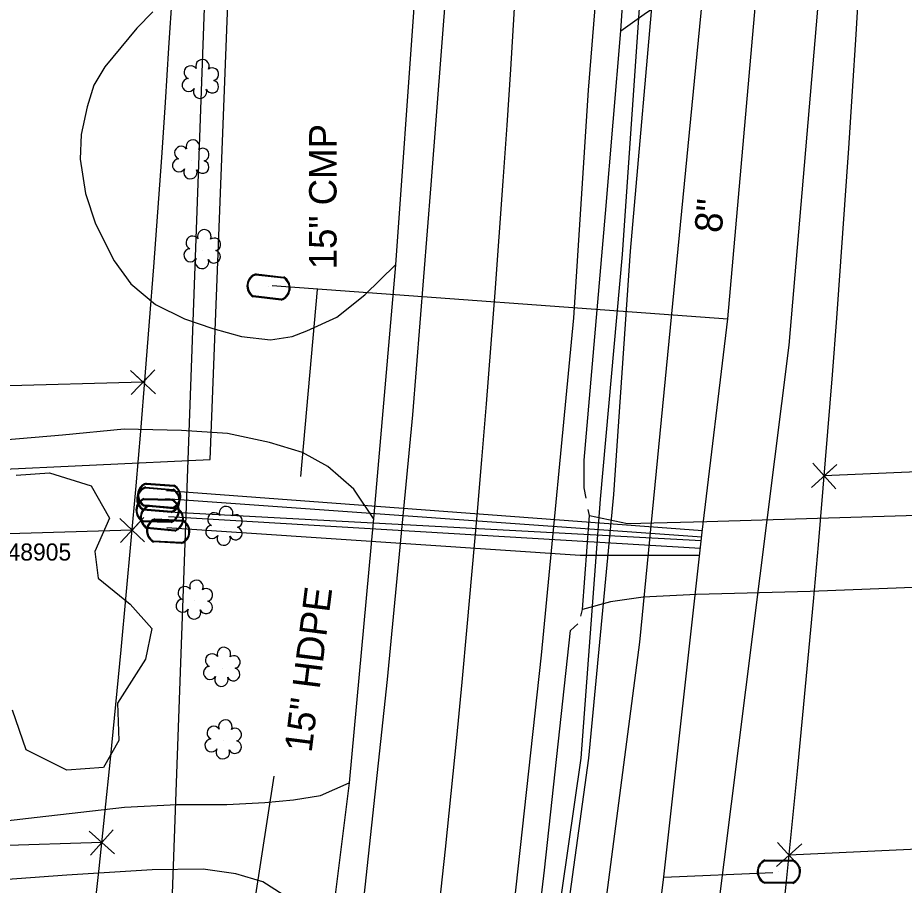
# Model space of a CAD drawing. Extents: x 3040896 to 3051146, y 687568 to 732976.
# Drawn here: x 3050359.9 to 3050489.4, y 692126.7 to 692253.4 of the extents above; entities that cross this region are included whole.
import ezdxf

# ---------------------------------------------------------------- set-up
doc = ezdxf.new("R2010")
doc.units = 0
for name, color, linetype in [('Exist Horizontal Alignment', 7, 'Continuous'), ('Exist Property Corner CELL', 7, 'Continuous'), ('Exist Property Line', 7, 'Continuous'), ('Exist Right of Way Easement Line', 7, 'Continuous'), ('Exist Right of Way Line', 7, 'Continuous'), ('Exist Roads Change in Surface', 7, 'Continuous'), ('Exist Roads EOP', 7, 'Continuous'), ('Exist Roads EOP Other', 7, 'Continuous'), ('Exist Roads EOT', 7, 'Continuous'), ('Exist Roads Soil', 7, 'Continuous'), ('Exist Structure Minor Pipes CMP 15 Inch', 7, 'Continuous'), ('Exist Structure Minor Pipes CMP 15 Inch Text', 7, 'Continuous'), ('Exist Structure Minor Pipes HDPE 15 Inch', 7, 'Continuous'), ('Exist Structure Minor Pipes HDPE 15 Inch Text', 7, 'Continuous'), ('Exist Utilities Power Joint Use Telephone Cogo Comment', 7, 'Continuous'), ('Exist Utilities Telephone UG Cable', 7, 'Continuous'), ('Exist Utilities Telephone UG Conduit SUE', 7, 'Continuous'), ('Exist Utilities Water Meter CELL', 7, 'Continuous'), ('Exist Utilities Water UG Line SUE', 7, 'Continuous'), ('Exist Utilities Water UG Line SUE Text', 7, 'Continuous'), ('Exist Vegetation Hedge Row', 7, 'Continuous'), ('Exist Vegetation Shrub CELL', 7, 'Continuous')]:
    doc.layers.add(name, color=color, linetype=linetype)

msp = doc.modelspace()

# ---------------------------------------------------------------- linework, layer by layer
at = {"layer": 'Exist Horizontal Alignment'}
msp.add_arc((3047548.29, 692429.83), 2889.5, 341.451, 2.18494, dxfattribs=at)
at = {"layer": 'Exist Property Corner CELL'}
for p, q in [((3050378.24, 692200.16), (3050378.24, 692200.16)), ((3050477.7, 692186.44), (3050477.7, 692186.44)), ((3050376.65, 692178.54), (3050376.65, 692178.54)), ((3050372.22, 692132.91), (3050372.22, 692132.91)), ((3050472.57, 692131.06), (3050472.57, 692131.06))]:
    msp.add_line(p, q, dxfattribs=at)
for points in [[(3050376.52, 692198.34), (3050379.95, 692201.97), (3050378.24, 692200.16), (3050376.42, 692201.87), (3050380.05, 692198.44)], [(3050476.03, 692188.3), (3050479.37, 692184.58), (3050477.7, 692186.44), (3050479.56, 692188.11), (3050475.84, 692184.77)], [(3050374.94, 692176.72), (3050378.36, 692180.36), (3050376.65, 692178.54), (3050374.83, 692180.25), (3050378.47, 692176.83)], [(3050374.08, 692131.24), (3050370.37, 692134.59), (3050372.22, 692132.91), (3050370.55, 692131.06), (3050373.9, 692134.77)], [(3050470.9, 692132.92), (3050474.24, 692129.2), (3050472.57, 692131.06), (3050474.43, 692132.73), (3050470.71, 692129.39)]]:
    msp.add_lwpolyline(points, dxfattribs=at)
at = {"layer": 'Exist Property Line'}
for p, q in [((3050378.24, 692200.16), (3050092.29, 692192.16)), ((3050586.46, 692191.46), (3050477.7, 692186.44)), ((3050376.65, 692178.54), (3050103.02, 692170.18)), ((3050609.02, 692137.42), (3050472.57, 692131.06))]:
    msp.add_line(p, q, dxfattribs=at)
at = {"layer": 'Exist Right of Way Easement Line'}
msp.add_line((3050372.22, 692132.91), (3049833.74, 692116.46), dxfattribs=at)
at = {"layer": 'Exist Right of Way Line'}
for radius in [2939.5, 2839.5]:
    msp.add_arc((3047548.29, 692429.83), radius, 341.451, 2.18494, dxfattribs=at)
at = {"layer": 'Exist Roads Change in Surface'}
msp.add_lwpolyline([(3050442.16, 692165.96), (3050442.41, 692166.93), (3050443.42, 692180.65), (3050443.25, 692181.54)], dxfattribs=at)
at = {"layer": 'Exist Roads EOP'}
for points in [[(3050442.94, 692183.19), (3050442.64, 692184.72), (3050442.67, 692188.75), (3050445.75, 692224.78), (3050448.02, 692251.48), (3050450.28, 692285.57), (3050451.67, 692312.92), (3050452.54, 692332.34), (3050452.6, 692339.09)], [(3050422.57, 692333.6), (3050421.5, 692308.19), (3050419.78, 692278.79), (3050417.77, 692254.87), (3050415.09, 692217.27), (3050411.91, 692180.22), (3050408.34, 692141.62), (3050405.23, 692116.7), (3050399.7, 692069.33), (3050393.06, 692018.15), (3050381.68, 691947.12), (3050378.88, 691928.21), (3050374.32, 691903.28), (3050369.25, 691876.97), (3050364.29, 691851.91)], [(3050431.59, 692084.53), (3050436.86, 692128.88), (3050440.66, 692163.88), (3050441.74, 692164.87)]]:
    msp.add_lwpolyline(points, dxfattribs=at)
at = {"layer": 'Exist Roads EOP Other'}
for points in [[(3050443.42, 692180.65), (3050448.98, 692179.5), (3050460.56, 692179.81), (3050489.68, 692180.66), (3050518.22, 692181.24), (3050547.88, 692182.08), (3050581.57, 692183.6), (3050589.57, 692183.89), (3050596.75, 692184.89), (3050606.36, 692186.1), (3050616.41, 692188.04), (3050625.67, 692188.73), (3050626.42, 692177.84)], [(3050613.16, 692158.9), (3050612.58, 692160.76), (3050612.11, 692161.63), (3050611.46, 692161.59), (3050610.6, 692161.03), (3050610.09, 692160.39), (3050609.91, 692157.91), (3050610.52, 692146.62), (3050596.9, 692147.08), (3050595.89, 692162.54), (3050595.39, 692166.27), (3050594.24, 692169.11), (3050591.91, 692171.51), (3050588.91, 692172.01), (3050579.02, 692172.64), (3050561.96, 692172.23), (3050534.74, 692171.42), (3050508.24, 692170.84), (3050475.63, 692169.59), (3050459.05, 692169.11), (3050451.24, 692168.72), (3050446.51, 692168.05), (3050442.41, 692166.93)]]:
    msp.add_lwpolyline(points, dxfattribs=at)
at = {"layer": 'Exist Roads EOT'}
for points in [[(3050449.05, 692339.54), (3050448.1, 692317.88), (3050446.24, 692280.17), (3050443.24, 692242.79), (3050441.08, 692209.53), (3050436.36, 692160.26), (3050432.05, 692120.59), (3050425.16, 692066.08), (3050419.53, 692024.14), (3050413.73, 691982.55), (3050409.13, 691952.43), (3050402.69, 691913.44), (3050391.31, 691854.27)], [(3050368.77, 691852.55), (3050373.59, 691877.32), (3050380.16, 691912.36), (3050387.83, 691958.96), (3050395.57, 692010.64), (3050401.4, 692052.65), (3050408.86, 692109.62), (3050413.93, 692156.72), (3050417.61, 692195.38), (3050420.31, 692228.98), (3050423.36, 692268.7), (3050425.33, 692301.17), (3050426.65, 692324.44), (3050427.1, 692337.22)]]:
    msp.add_lwpolyline(points, dxfattribs=at)
at = {"layer": 'Exist Roads Soil'}
for points in [[(3050448.02, 692251.48), (3050451.42, 692253.9), (3050457.3, 692257.93), (3050461.36, 692260.71), (3050465.66, 692262.56), (3050471.5, 692264.21), (3050478.88, 692265.17), (3050491.2, 692266.01), (3050509.69, 692267.28), (3050525.16, 692267.64), (3050540.16, 692267.69), (3050554.94, 692268.35), (3050563.52, 692268.52), (3050570.07, 692268.32), (3050575.47, 692267.56), (3050578.65, 692266.71), (3050582.07, 692265.2), (3050584.54, 692263.58), (3050586.28, 692261.68), (3050587.6, 692258.53), (3050588.62, 692252.04), (3050590.27, 692234.67), (3050601.02, 692235.41)], [(3050379.65, 692254.24), (3050377.35, 692251.87), (3050372.66, 692246.22), (3050371.04, 692243.5), (3050370.1, 692240.37), (3050369.22, 692236.34), (3050369.06, 692232.71), (3050369.86, 692227.69), (3050371.32, 692223.27), (3050374, 692217.88), (3050376.44, 692214.53), (3050380.06, 692211.51), (3050384.28, 692209.38), (3050388.45, 692207.96), (3050392.6, 692206.79), (3050396.85, 692206.33), (3050400.03, 692206.8), (3050402.14, 692207.64), (3050406.52, 692209.65), (3050410.62, 692212.9), (3050415.09, 692217.27)], [(3050411.91, 692180.22), (3050409.01, 692184.5), (3050405.21, 692187.81), (3050401.5, 692189.86), (3050396.68, 692191.34), (3050390.56, 692192.63), (3050383.85, 692193.07), (3050375.49, 692193.26), (3050366.5, 692192.42), (3050350.98, 692191.07)], [(3050334.99, 692133.39), (3050362.76, 692136.6), (3050375.53, 692138.08), (3050383.17, 692138.45), (3050390.45, 692138.48), (3050396.03, 692138.76), (3050400.21, 692139.14), (3050404.13, 692139.76), (3050408.34, 692141.62)], [(3050405.23, 692116.7), (3050402.58, 692121.95), (3050398.68, 692125.25), (3050395.74, 692127.16), (3050391.79, 692128.35), (3050387.02, 692129.03), (3050379.59, 692128.92), (3050367.12, 692128.16), (3050345.14, 692126.51)]]:
    msp.add_lwpolyline(points, dxfattribs=at)
at = {"layer": 'Exist Structure Minor Pipes CMP 15 Inch'}
msp.add_lwpolyline([(3050403.68, 692213.69), (3050401.21, 692186.38)], dxfattribs=at)
at = {"layer": 'Exist Structure Minor Pipes HDPE 15 Inch'}
msp.add_lwpolyline([(3050397.35, 692142.62), (3050394.54, 692124.61)], dxfattribs=at)
at = {"layer": 'Exist Utilities Telephone UG Cable'}
for points in [[(3050413.62, 691781.42), (3050411.67, 691787.91), (3050393.18, 691793.16), (3050421.6, 691924.67), (3050440.31, 692081.94), (3050450.77, 692162.15), (3050462.5, 692282.64), (3050475.19, 692282.32), (3050482.17, 692286.76)], [(3050413.62, 691781.42), (3050450.45, 692029.34), (3050472.57, 692205.55), (3050478.99, 692280.93), (3050482.17, 692286.76)], [(3049596.71, 692158.55), (3049598.34, 692164.45), (3049874.82, 692169.21), (3049874.93, 692164.81), (3049877.04, 692169.53), (3050100.49, 692176.11), (3050101.16, 692172.77), (3050103.16, 692176.4), (3050350.02, 692187.28), (3050352.4, 692180.56), (3050354.81, 692187.28), (3050388.06, 692188.83), (3050391.45, 692276.76), (3050388.17, 692281.77)], [(3050260.31, 691564.78), (3050289.07, 691666.99), (3050266.25, 691669.84), (3050263.01, 691676.7), (3050381.82, 692105.25), (3050388.17, 692281.77)]]:
    msp.add_lwpolyline(points, dxfattribs=at)
at = {"layer": 'Exist Utilities Telephone UG Conduit SUE'}
for points in [[(3050204.31, 691198.02), (3050217.33, 691238.61), (3050246.99, 691329.68), (3050255.16, 691354.24), (3050257.11, 691359.81), (3050285.66, 691445.56), (3050311.85, 691526.82), (3050319.54, 691550.7), (3050333.71, 691593.52), (3050346.78, 691641.84), (3050376.07, 691748.7), (3050384.66, 691782.86), (3050394.28, 691828.2), (3050407.75, 691884.37), (3050416.04, 691929.41), (3050421.75, 691968.35), (3050431.44, 692052.97), (3050437.86, 692105.62), (3050443.35, 692145.22), (3050446.97, 692183.73), (3050449.41, 692219.29), (3050453.06, 692261.01)], [(3050282.17, 691445.38), (3050309.77, 691524.06), (3050318.46, 691550.99), (3050331, 691593.08), (3050345.78, 691642), (3050374.75, 691747.94), (3050383.05, 691783.78), (3050392.62, 691827.48), (3050403.52, 691884.08), (3050414.14, 691928.34), (3050419.9, 691970.04), (3050436.56, 692105.97), (3050442.19, 692145.22), (3050445.05, 692183.04), (3050448.26, 692218.8), (3050451.11, 692260.46)]]:
    msp.add_lwpolyline(points, dxfattribs=at)
at = {"layer": 'Exist Utilities Water Meter CELL'}
for p, q in [((3050396.57, 692214.05), (3050396.57, 692214.05)), ((3050380.6, 692183.56), (3050380.6, 692183.56)), ((3050380.47, 692182.97), (3050380.47, 692182.97)), ((3050380.37, 692181.4), (3050380.37, 692181.4)), ((3050381, 692180.28), (3050381, 692180.28)), ((3050381.92, 692178.39), (3050381.92, 692178.39)), ((3050471.08, 692128.65), (3050471.08, 692128.65))]:
    msp.add_line(p, q, dxfattribs=at)
for points in [[(3050394.73, 692215.84), (3050398.77, 692215.36)], [(3050394.74, 692215.97), (3050398.79, 692215.5)], [(3050398.39, 692212.12), (3050394.32, 692212.6)], [(3050398.41, 692212.26), (3050394.34, 692212.74)], [(3050378.57, 692184.69), (3050382.63, 692184.36)], [(3050378.58, 692184.83), (3050382.64, 692184.49)], [(3050378.69, 692185.27), (3050382.75, 692184.96)], [(3050378.7, 692185.41), (3050382.76, 692185.1)], [(3050378.37, 692183.15), (3050382.44, 692183.06)], [(3050378.37, 692183.02), (3050382.44, 692182.92)], [(3050382.5, 692181.71), (3050378.41, 692182.02)], [(3050382.51, 692181.84), (3050378.42, 692182.16)], [(3050379.11, 692182.03), (3050383.17, 692181.65)], [(3050379.13, 692182.16), (3050383.18, 692181.79)], [(3050382.36, 692181.1), (3050378.27, 692181.44)], [(3050382.37, 692181.24), (3050378.28, 692181.58)], [(3050382.36, 692179.66), (3050378.26, 692179.75)], [(3050382.37, 692179.79), (3050378.27, 692179.89)], [(3050379.96, 692180.05), (3050384.03, 692179.84)], [(3050379.97, 692180.19), (3050384.04, 692179.98)], [(3050382.87, 692178.4), (3050378.79, 692178.78)], [(3050382.89, 692178.54), (3050378.8, 692178.92)], [(3050383.87, 692176.59), (3050379.77, 692176.8)], [(3050383.87, 692176.72), (3050379.78, 692176.93)], [(3050469.04, 692130.35), (3050473.11, 692130.35)], [(3050469.04, 692130.21), (3050473.11, 692130.21)], [(3050473.11, 692127.09), (3050469.01, 692127.09)], [(3050473.11, 692126.95), (3050469.01, 692126.95)]]:
    msp.add_lwpolyline(points, dxfattribs=at)
for centre, radius, start, end in [((3050395.27, 692214.2), 1.86, 106.4868, 239.2881), ((3050395.28, 692214.19), 1.73, 108.6097, 237.0911), ((3050397.85, 692213.9), 1.86, 286.9571, 59.6171), ((3050397.86, 692213.9), 1.73, 288.4359, 58.1816), ((3050379.17, 692183.07), 1.86, 108.4536, 241.2549), ((3050379.3, 692183.65), 1.86, 108.8165, 241.6178), ((3050379.18, 692183.07), 1.73, 110.5765, 239.0579), ((3050379.31, 692183.65), 1.73, 110.9394, 239.4208), ((3050381.76, 692182.86), 1.86, 288.9239, 61.5839), ((3050381.89, 692183.46), 1.86, 289.2867, 61.9468), ((3050381.9, 692183.46), 1.73, 290.7656, 60.5113), ((3050379.06, 692181.43), 1.86, 111.8141, 244.6155), ((3050381.77, 692182.86), 1.73, 290.4027, 60.1484), ((3050379.07, 692181.43), 1.73, 113.937, 242.4184), ((3050379.7, 692180.4), 1.86, 107.9309, 240.7323), ((3050379.71, 692180.4), 1.73, 110.0538, 238.5352), ((3050381.66, 692181.37), 1.86, 292.2844, 64.9444), ((3050381.67, 692181.37), 1.73, 293.7632, 63.5089), ((3050382.29, 692180.17), 1.86, 288.4012, 61.0612), ((3050382.3, 692180.16), 1.73, 289.88, 59.6257), ((3050380.61, 692178.45), 1.86, 110.2348, 243.0362), ((3050380.62, 692178.45), 1.73, 112.3577, 240.8391), ((3050383.21, 692178.32), 1.86, 290.7051, 63.3652), ((3050383.22, 692178.32), 1.73, 292.1839, 61.9296), ((3050469.77, 692128.65), 1.86, 113.178, 245.9794), ((3050469.78, 692128.65), 1.73, 115.3009, 243.7824), ((3050472.37, 692128.65), 1.86, 293.6483, 66.3084), ((3050472.38, 692128.65), 1.73, 295.1272, 64.8728)]:
    msp.add_arc(centre, radius, start, end, dxfattribs=at)
at = {"layer": 'Exist Utilities Water UG Line SUE'}
msp.add_line((3050397.07, 692214.24), (3050463.63, 692209.38), dxfattribs=at)
for points in [[(3050459.9, 692178.26), (3050463.63, 692209.38), (3050468.31, 692262.6)], [(3050381.53, 692183.16), (3050459.82, 692177.54)], [(3050381.66, 692184.31), (3050459.93, 692178.46)], [(3050381.98, 692180.54), (3050459.64, 692175.88)], [(3050382.01, 692181.22), (3050459.76, 692177)], [(3050381.73, 692178.9), (3050442.08, 692174.87), (3050459.53, 692174.9)], [(3050454.22, 692127.47), (3050459.9, 692178.26)], [(3050432.66, 691967.23), (3050435.43, 691986.86), (3050443.19, 692044.43), (3050447.3, 692072.18), (3050454.22, 692127.47)], [(3050454.26, 692127.83), (3050470.21, 692128.51)]]:
    msp.add_lwpolyline(points, dxfattribs=at)
at = {"layer": 'Exist Vegetation Hedge Row'}
for points in [[(3050359.71, 692186.58), (3050364.58, 692186.91), (3050370.66, 692185.01), (3050373.34, 692180.28), (3050371.21, 692175.4), (3050371.7, 692171.51)], [(3050371.7, 692171.51), (3050376.35, 692167.71), (3050379.52, 692164.19), (3050378.58, 692159.68), (3050374.53, 692153.26), (3050374.72, 692147.83), (3050372.48, 692143.87), (3050367.1, 692143.49), (3050361.19, 692146.43), (3050359.2, 692152.22)]]:
    msp.add_lwpolyline(points, dxfattribs=at)
at = {"layer": 'Exist Vegetation Shrub CELL'}
for p, q in [((3050386.69, 692244.25), (3050386.69, 692244.25)), ((3050385.28, 692232.5), (3050385.28, 692232.5)), ((3050386.96, 692219.39), (3050386.96, 692219.39)), ((3050390.13, 692178.98), (3050390.13, 692178.98)), ((3050385.81, 692168.2), (3050385.81, 692168.2)), ((3050389.81, 692158.39), (3050389.81, 692158.39)), ((3050390.03, 692147.79), (3050390.03, 692147.79))]:
    msp.add_line(p, q, dxfattribs=at)
for centre, radius, start, end in [((3050386.92, 692246.29), 0.99, 334.8391, 200.4717), ((3050385.21, 692245.38), 0.968, 35.8908, 245.4216), ((3050388.36, 692245.12), 0.929, 284.4567, 126.0861), ((3050384.89, 692243.54), 0.955, 95.1099, 327.9534), ((3050388.33, 692243.32), 0.937, 204.9913, 73.4601), ((3050386.56, 692242.57), 0.984, 151.2797, 21.387), ((3050385.51, 692234.55), 0.99, 334.8391, 200.4717), ((3050383.8, 692233.63), 0.968, 35.8908, 245.4216), ((3050386.95, 692233.37), 0.929, 284.4567, 126.0861), ((3050383.48, 692231.8), 0.955, 95.1099, 327.9534), ((3050386.92, 692231.58), 0.937, 204.9913, 73.4601), ((3050385.15, 692230.82), 0.984, 151.2797, 21.387), ((3050387.19, 692221.44), 0.99, 334.8391, 200.4717), ((3050385.48, 692220.52), 0.968, 35.8908, 245.4216), ((3050388.64, 692220.26), 0.929, 284.4567, 126.0861), ((3050385.16, 692218.69), 0.955, 95.1099, 327.9534), ((3050386.84, 692217.71), 0.984, 151.2797, 21.387), ((3050388.6, 692218.47), 0.937, 204.9913, 73.4601), ((3050390.36, 692181.02), 0.99, 334.8391, 200.4717), ((3050388.65, 692180.11), 0.968, 35.8908, 245.4216), ((3050391.81, 692179.85), 0.929, 284.4567, 126.0861), ((3050388.33, 692178.28), 0.955, 95.1099, 327.9534), ((3050391.77, 692178.05), 0.937, 204.9913, 73.4601), ((3050390.01, 692177.3), 0.984, 151.2797, 21.387), ((3050384.33, 692169.33), 0.968, 35.8908, 245.4216), ((3050386.04, 692170.24), 0.99, 334.8391, 200.4717), ((3050387.48, 692169.07), 0.929, 284.4567, 126.0861), ((3050384.01, 692167.5), 0.955, 95.1099, 327.9534), ((3050387.44, 692167.27), 0.937, 204.9913, 73.4601), ((3050385.68, 692166.52), 0.984, 151.2797, 21.387), ((3050390.04, 692160.43), 0.99, 334.8391, 200.4717), ((3050388.32, 692159.51), 0.968, 35.8908, 245.4216), ((3050391.48, 692159.26), 0.929, 284.4567, 126.0861), ((3050388.01, 692157.68), 0.955, 95.1099, 327.9534), ((3050391.44, 692157.46), 0.937, 204.9913, 73.4601), ((3050389.68, 692156.7), 0.984, 151.2797, 21.387), ((3050390.26, 692149.83), 0.99, 334.8391, 200.4717), ((3050388.55, 692148.92), 0.968, 35.8908, 245.4216), ((3050391.7, 692148.66), 0.929, 284.4567, 126.0861), ((3050388.23, 692147.09), 0.955, 95.1099, 327.9534), ((3050391.67, 692146.86), 0.937, 204.9913, 73.4601), ((3050389.9, 692146.11), 0.984, 151.2797, 21.387)]:
    msp.add_arc(centre, radius, start, end, dxfattribs=at)

# ---------------------------------------------------------------- texts
at = {"layer": 'Exist Structure Minor Pipes CMP 15 Inch Text'}
msp.add_text('15" CMP', height=4, rotation=90, dxfattribs=at).set_placement((3050406.49, 692216.63))
at = {"layer": 'Exist Structure Minor Pipes HDPE 15 Inch Text'}
msp.add_text('15" HDPE', height=4, rotation=82.7978, dxfattribs=at).set_placement((3050402.84, 692145.95))
at = {"layer": 'Exist Utilities Power Joint Use Telephone Cogo Comment'}
msp.add_text('TV748905', height=2.5, dxfattribs=at).set_placement((3050352.32, 692174.09))
at = {"layer": 'Exist Utilities Water UG Line SUE Text'}
msp.add_text('8"', height=4, rotation=84.9806, dxfattribs=at).set_placement((3050462.72, 692221.85))

doc.saveas('drawing.dxf')
